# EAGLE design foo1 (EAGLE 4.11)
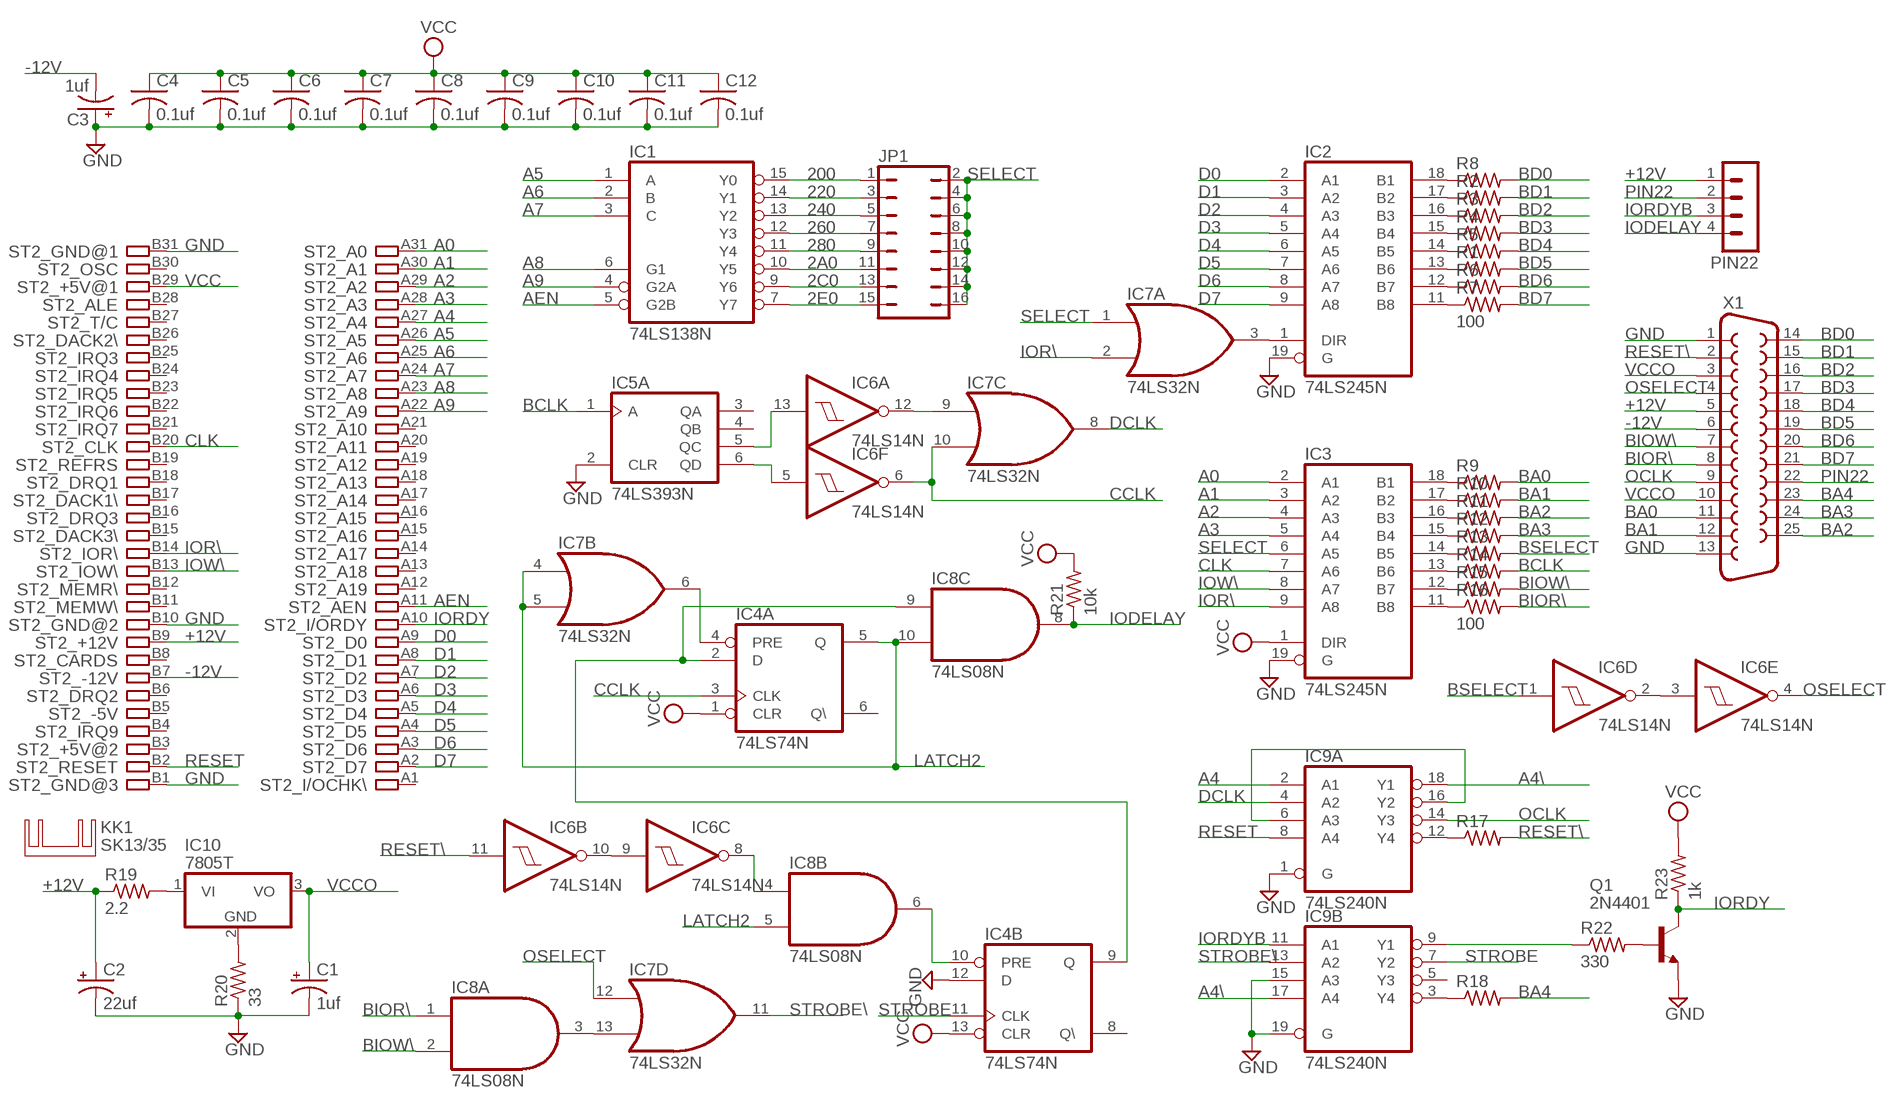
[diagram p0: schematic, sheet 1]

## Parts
C1  1uf  CPOL-USE5-10.5  [E5-10,5]
C2  22uf  CPOL-USE5-10.5  [E5-10,5]
C3  1uf  CPOL-USE5-10.5  [E5-10,5]
C4  0.1uf  C-US050-025X075  [C050-025X075]
C5  0.1uf  C-US050-025X075  [C050-025X075]
C6  0.1uf  C-US050-025X075  [C050-025X075]
C7  0.1uf  C-US050-025X075  [C050-025X075]
C8  0.1uf  C-US050-025X075  [C050-025X075]
C9  0.1uf  C-US050-025X075  [C050-025X075]
C10  0.1uf  C-US050-025X075  [C050-025X075]
C11  0.1uf  C-US050-025X075  [C050-025X075]
C12  0.1uf  C-US050-025X075  [C050-025X075]
IC1  74LS138N  [DIL16]
IC2  74LS245N  [DIL20]
IC3  74LS245N  [DIL20]
IC4  74LS74N  [DIL14]
IC5  74LS393N  [DIL14]
IC6  74LS14N  [DIL14]
IC7  74LS32N  [DIL14]
IC8  74LS08N  [DIL14]
IC9  74LS240N  [DIL20]
IC10  7805T  [TO220H]
JP1  JP8Q  [JP8Q]
KK1  SK13/35  [SK13/35]
PIN22  MA04-1  [MA04-1]
Q1  2N4401  2N4416  [TO92]
R1  R-US_0207/10  [0207/10]
R2  R-US_0207/10  [0207/10]
R3  R-US_0207/10  [0207/10]
R4  R-US_0207/10  [0207/10]
R5  R-US_0207/10  [0207/10]
R6  R-US_0207/10  [0207/10]
R7  100  R-US_0207/10  [0207/10]
R8  R-US_0207/10  [0207/10]
R9  R-US_0207/10  [0207/10]
R10  R-US_0207/10  [0207/10]
R11  R-US_0207/10  [0207/10]
R12  R-US_0207/10  [0207/10]
R13  R-US_0207/10  [0207/10]
R14  R-US_0207/10  [0207/10]
R15  R-US_0207/10  [0207/10]
R16  100  R-US_0207/10  [0207/10]
R17  R-US_0207/10  [0207/10]
R18  R-US_0207/10  [0207/10]
R19  2.2  R-US_0613/15  [P0613/15]
R20  33  R-US_0207/10  [0207/10]
R21  10k  R-US_0207/10  [0207/10]
R22  330  R-US_0207/10  [0207/10]
R23  1k  R-US_0207/10  [0207/10]
ST2  IBM8BIT  [IBM8BIT]
X1  F25H  [F25H]

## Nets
2A0: IC1.10(Y5) JP1.11
2C0: IC1.9(Y6) JP1.13
2E0: IC1.7(Y7) JP1.15
200: IC1.15(Y0) JP1.1
220: IC1.14(Y1) JP1.3
240: IC1.13(Y2) JP1.5
260: IC1.12(Y3) JP1.7
280: IC1.11(Y4) JP1.9
+12V [Power]: C2.+ PIN22.1 R19.1 ST2.B9 X1.5
-12V [Power]: C3.- ST2.B7 X1.6
A0: IC3.2(A1) ST2.A31
A1: IC3.3(A2) ST2.A30
A2: IC3.4(A3) ST2.A29
A3: IC3.5(A4) ST2.A28
A4: IC9.2(A:A1) ST2.A27
A4\: IC9.17(B:A4) IC9.18(A:Y1)
A5: IC1.1(A) ST2.A26
A6: IC1.2(B) ST2.A25
A7: IC1.3(C) ST2.A24
A8: IC1.6(G1) ST2.A23
A9: IC1.4(G2A) ST2.A22
AEN: IC1.5(G2B) ST2.A11
BA0: R9.2 X1.11
BA1: R10.2 X1.12
BA2: R11.2 X1.25
BA3: R12.2 X1.24
BA4: R18.2 X1.23
BCLK: IC5.1(A:A) R14.2
BD0: R8.2 X1.14
BD1: R2.2 X1.15
BD2: R3.2 X1.16
BD3: R4.2 X1.17
BD4: R5.2 X1.18
BD5: R1.2 X1.19
BD6: R6.2 X1.20
BD7: R7.2 X1.21
BIOR\: IC8.1(A:I0) R16.2 X1.8
BIOW\: IC8.2(A:I1) R15.2 X1.7
BSELECT: IC6.1(D:I) R13.2
CCLK: IC4.3(A:CLK) IC6.6(F:O) IC7.10(C:I1)
CLK: IC3.7(A6) ST2.B20
D0: IC2.2(A1) ST2.A9
D1: IC2.3(A2) ST2.A8
D2: IC2.4(A3) ST2.A7
D3: IC2.5(A4) ST2.A6
D4: IC2.6(A5) ST2.A5
D5: IC2.7(A6) ST2.A4
D6: IC2.8(A7) ST2.A3
D7: IC2.9(A8) ST2.A2
DCLK: IC7.8(C:O) IC9.4(A:A2)
GND [Power]: C1.- C2.- C3.+ C4.2 C5.2 C6.2 C7.2 C8.2 C9.2 C10.2 C11.2 C12.2 IC2.19(G) IC3.19(G) IC4.12(B:D) IC5.2(A:CLR) IC9.1(A:G) IC9.15(B:A3) IC9.19(B:G) Q1.3(E) R20.1 ST2.B1 ST2.B10 ST2.B31 X1.1 X1.13
IODELAY: IC8.8(C:O) PIN22.4 R21.1
IOR\: IC3.9(A8) IC7.2(A:I1) ST2.B14
IORDY: Q1.1(C) R23.1 ST2.A10
IORDYB: IC9.11(B:A1) PIN22.3
IOW\: IC3.8(A7) ST2.B13
LATCH2: IC4.5(A:Q) IC7.4(B:I0) IC7.5(B:I1) IC8.5(B:I1) IC8.10(C:I1)
N$1: IC2.1(DIR) IC7.3(A:O)
N$2 [Power]: IC10.2(GND) R20.2
N$3: IC2.13(B6) R1.1
N$4: IC2.17(B2) R2.1
N$5: IC2.16(B3) R3.1
N$6: IC2.15(B4) R4.1
N$7: IC2.14(B5) R5.1
N$8: IC2.12(B7) R6.1
N$9: IC2.11(B8) R7.1
N$10: IC2.18(B1) R8.1
N$11: IC3.18(B1) R9.1
N$12: IC3.17(B2) R10.1
N$13: IC3.16(B3) R11.1
N$14: IC3.15(B4) R12.1
N$15: IC3.14(B5) R13.1
N$16: IC3.13(B6) R14.1
N$17: IC3.12(B7) R15.1
N$18: IC3.11(B8) R16.1
N$19: IC9.12(A:Y4) R17.1
N$20: IC6.9(C:I) IC6.10(B:O)
N$21: IC6.2(D:O) IC6.3(E:I)
N$22: IC5.6(A:QD) IC6.5(F:I)
N$23: IC9.3(B:Y4) R18.1
N$24: IC5.5(A:QC) IC6.13(A:I)
N$25 [Power]: IC10.1(VI) R19.2
N$26: IC6.12(A:O) IC7.9(C:I0)
N$28: IC9.6(A:A3) IC9.16(A:Y2)
N$29: IC7.13(D:I1) IC8.3(A:O)
N$30: IC4.2(A:D) IC4.9(B:Q) IC8.9(C:I0)
N$32: IC9.9(B:Y1) R22.1
N$33: IC4.10(B:PRE) IC8.6(B:O)
N$34: IC6.8(C:O) IC8.4(B:I0)
N$36: IC4.4(A:PRE) IC7.6(B:O)
N$37: Q1.2(B) R22.2
OCLK: IC9.14(A:Y3) X1.9
OSELECT: IC6.4(E:O) IC7.12(D:I0) X1.4
PIN22: PIN22.2 X1.22
RESET: IC9.8(A:A4) ST2.B2
RESET\: IC6.11(B:I) R17.2 X1.2
SELECT: IC3.6(A5) IC7.1(A:I0) JP1.2 JP1.4 JP1.6 JP1.8 JP1.10 JP1.12 JP1.14 JP1.16
STROBE: IC4.11(B:CLK) IC9.7(B:Y2)
STROBE\: IC7.11(D:O) IC9.13(B:A2)
VCC [Power]: C4.1 C5.1 C6.1 C7.1 C8.1 C9.1 C10.1 C11.1 C12.1 IC3.1(DIR) IC4.1(A:CLR) IC4.13(B:CLR) R21.2 R23.2 ST2.B29
VCCO [Power]: C1.+ IC10.3(VO) X1.3 X1.10
Unconnected: IC4.6(A:Q\) IC4.8(B:Q\) IC5.3(A:QA) IC5.4(A:QB) IC5.8(B:QD) IC5.9(B:QC) IC5.10(B:QB) IC5.11(B:QA) IC5.12(B:CLR) IC5.13(B:A) IC8.11(D:O) IC8.12(D:I0) IC8.13(D:I1) IC9.5(B:Y3) ST2.A1 ST2.A12 ST2.A13 ST2.A14 ST2.A15 ST2.A16 ST2.A17 ST2.A18 ST2.A19 ST2.A20 ST2.A21 ST2.B3 ST2.B4 ST2.B5 ST2.B6 ST2.B8 ST2.B11 ST2.B12 ST2.B15 ST2.B16 ST2.B17 ST2.B18 ST2.B19 ST2.B21 ST2.B22 ST2.B23 ST2.B24 ST2.B25 ST2.B26 ST2.B27 ST2.B28 ST2.B30

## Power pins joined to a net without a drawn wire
GND: IC1.8(GND) IC2.10(GND) IC3.10(GND) IC4.7(P:GND) IC5.7(P:GND) IC6.7(P:GND) IC7.7(P:GND) IC8.7(P:GND) IC9.10(P:GND)
VCC: IC1.16(VCC) IC2.20(VCC) IC3.20(VCC) IC4.14(P:VCC) IC5.14(P:VCC) IC6.14(P:VCC) IC7.14(P:VCC) IC8.14(P:VCC) IC9.20(P:VCC)

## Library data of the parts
C1-C3 = rcl:CPOL-US: POLARIZED CAPACITOR, American symbol
C4-C12 = rcl:C-US: CAPACITOR, American symbol
IC1 = 74xx-us:74*138: 3-line to 8-line DECODER/DEMULTIPLEXER
IC2 IC3 = 74xx-us:74*245: Octal BUS TRANSCEIVER, 3-state
IC4 = 74xx-us:74*74: Dual D type positive edge triggered FLIP FLOP, preset and clear
IC5 = 74xx-us:74*393: Dual 4-bit decade and binary COUNTER
IC6 = 74xx-us:74*14: Hex schmitt trigger INVERTER
IC7 = 74xx-us:74*32: Quad 2-input OR gate
IC8 = 74xx-us:74*08: Quad 2-input AND gate
IC9 = 74xx-us:74*240: Octal BUFFER and LINE DRIVER, 3-state
IC10 = linear:78*: Positive VOLTAGE REGULATOR
JP1 = jumper:JP8Q: JUMPER
KK1 = heatsink:SK13/35: HEATSINK
PIN22 = con-lstb:MA04-1: PIN HEADER
Q1 = transistor-npn:2N4416: NPN Transistor
R1-R23 = rcl:R-US_: RESISTOR, American symbol
ST2 = con-pc:IBM8BIT: 8-bit CARD IBM/PC-AT
X1 = con-subd:F25: SUB-D

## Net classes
1 Power: width 0.762 mm, drill 0.254 mm

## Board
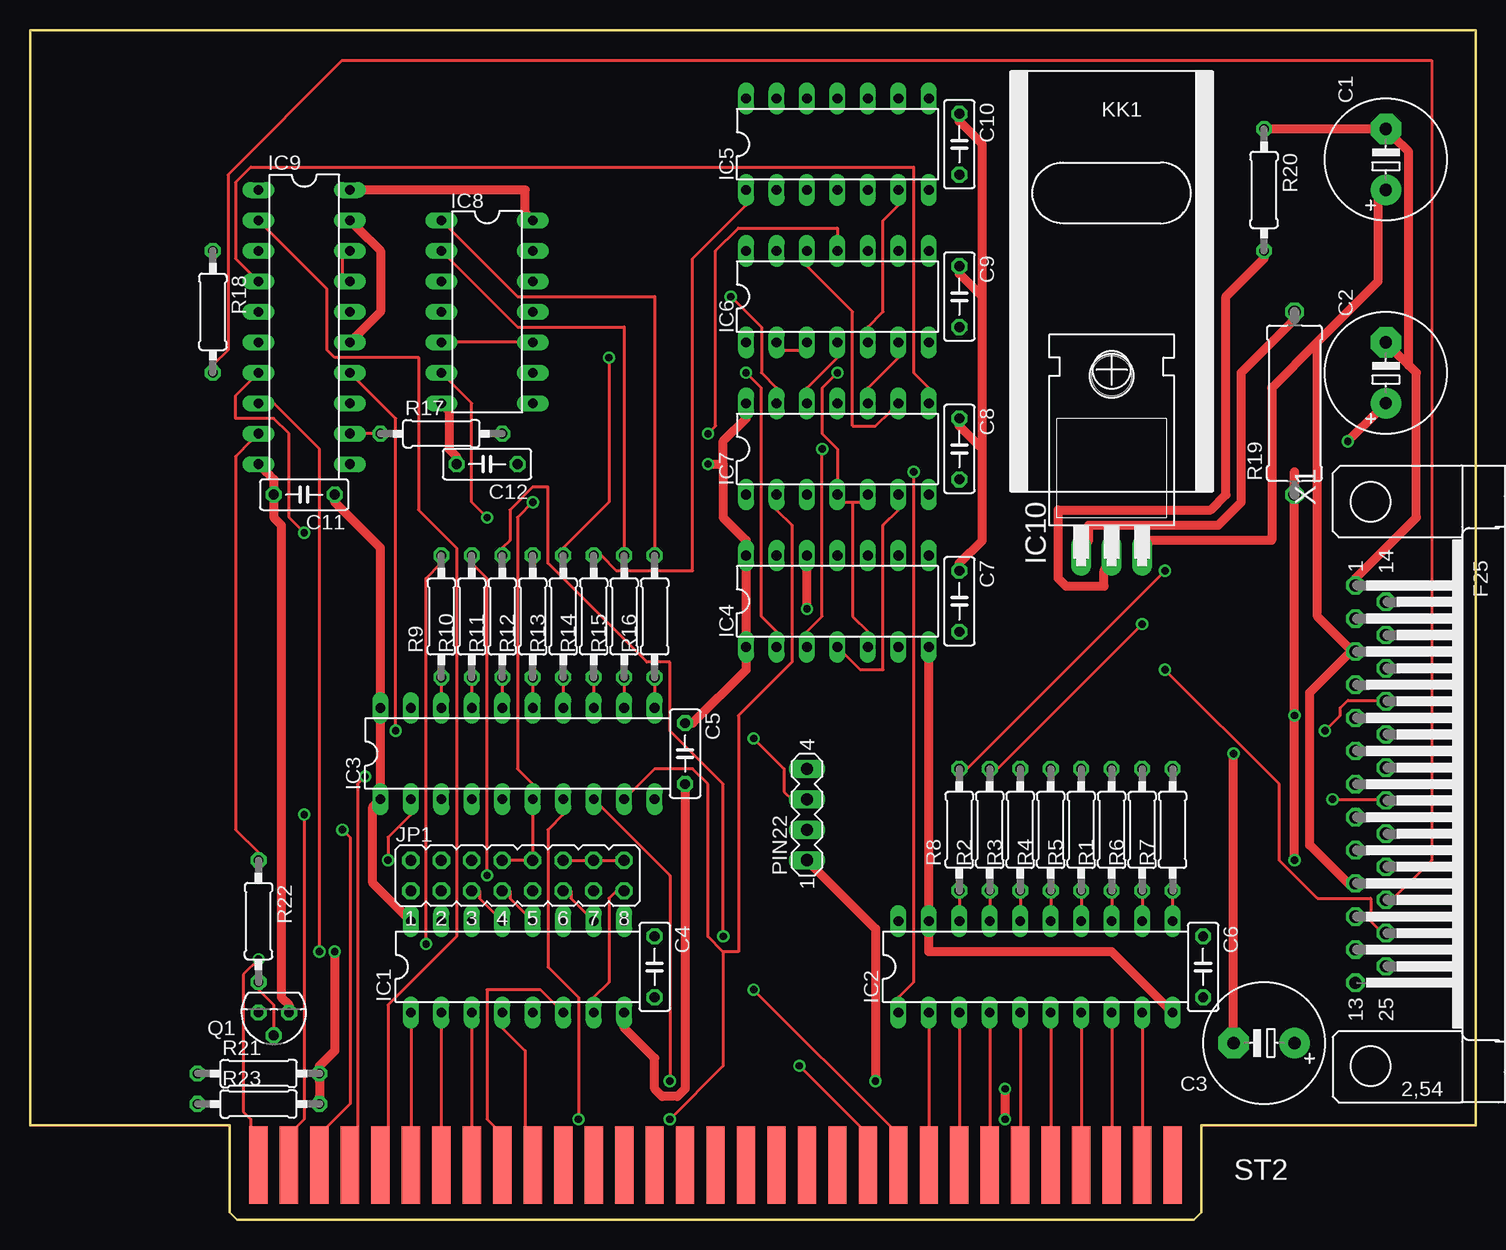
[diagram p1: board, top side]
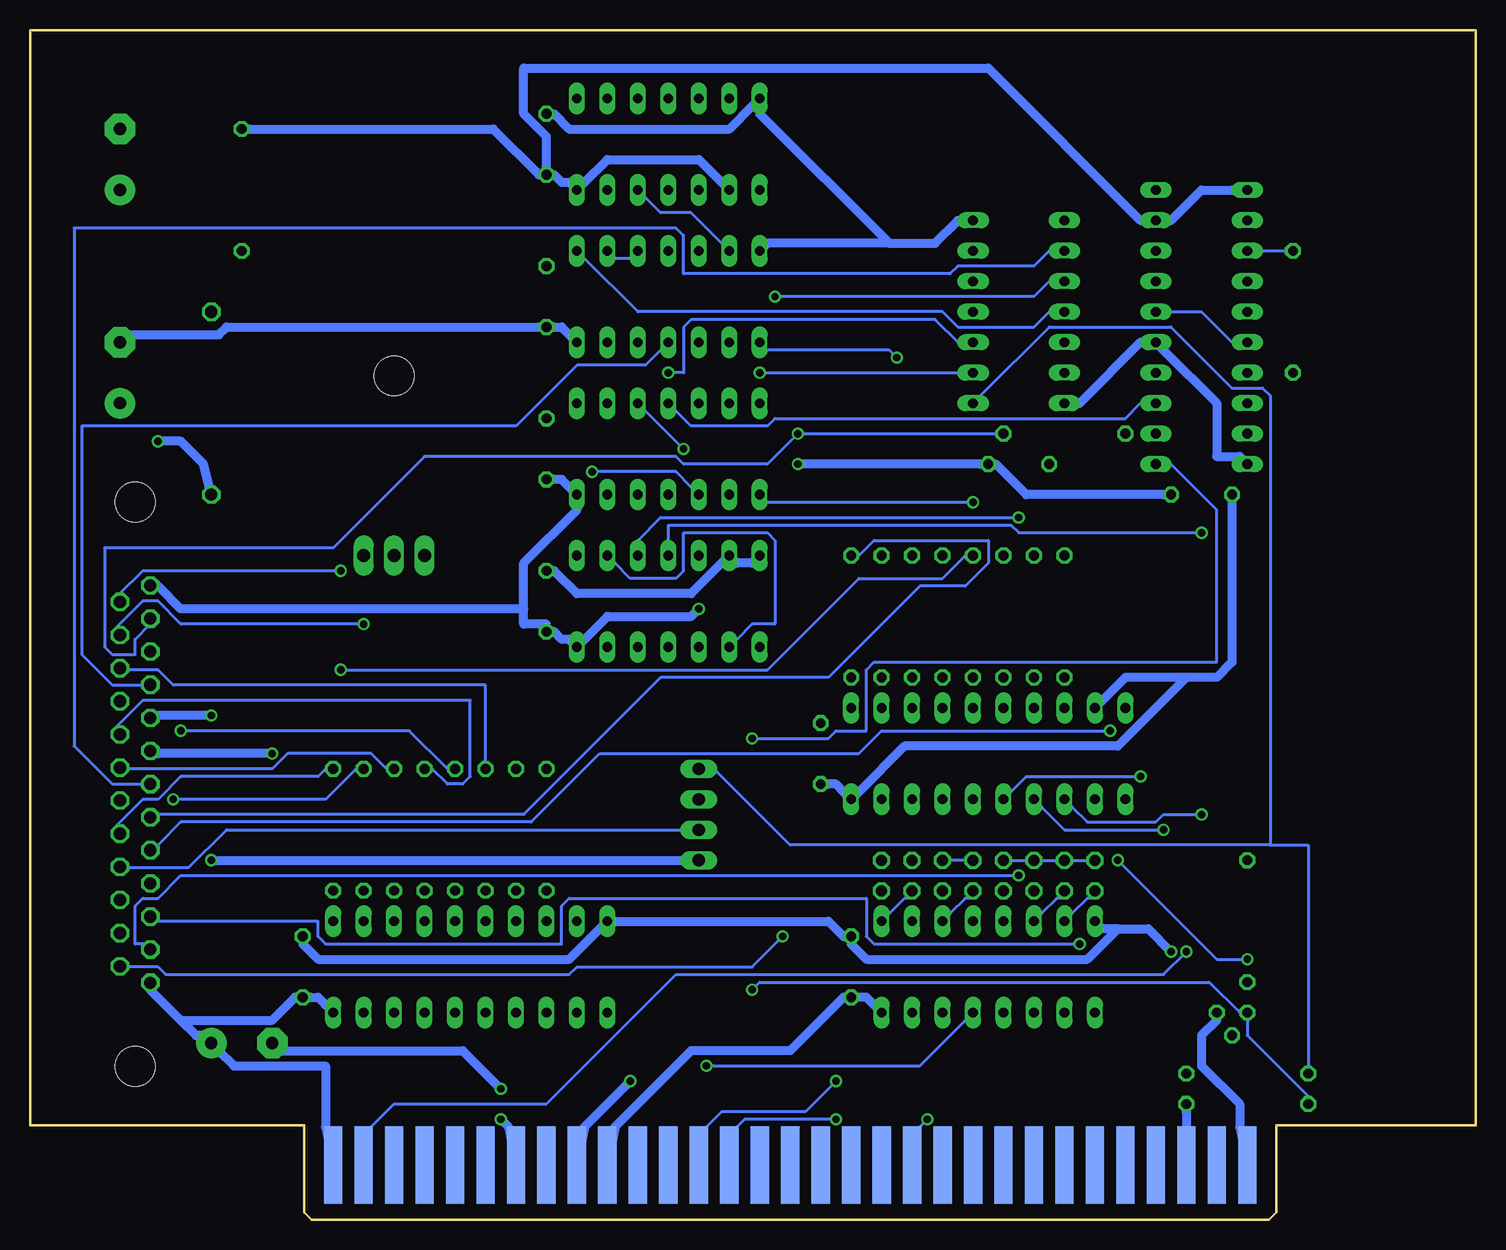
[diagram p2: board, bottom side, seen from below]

Size 120.52 x 99.19 mm. Coordinates in mm from the lower left corner, seen from the top.
Outline: 0,7.87 0,99.19 120.52,99.19 120.52,7.87 97.66,7.87 97.66,0.64 97.03,0 17.27,0 16.64,0.64 16.64,7.87 0.13,7.87
Copper layers (1*16): Top 0.035mm / dielectric 1.5mm / Bottom 0.035mm
Design rules "olimex10mil": minimum track width 10mil, minimum drill 24mil, track to track 10mil, track to pad 10mil, pad to pad 10mil, via to via 10mil, smd to smd 10mil, copper to edge 40mil, drill to drill 10mil, minimum pad ring 10mil, minimum via ring 8mil, stop-mask expansion 0mil, vias tented up to drill 0mil, thermal gap 10mil

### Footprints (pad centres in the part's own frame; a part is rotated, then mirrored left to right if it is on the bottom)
E5-10,5 = drill 1.016 pad 2.54 round: + -2.54,0 | drill 1.016 pad 2.54 octagon: - 2.54,0
C050-025X075 = drill 0.813 octagon: 1 -2.54,0; 2 2.54,0
DIL16 = drill 0.813 long: 1 -8.89,-3.81; 2 -6.35,-3.81; 3 -3.81,-3.81; 4 -1.27,-3.81; 5 1.27,-3.81; 6 3.81,-3.81; 7 6.35,-3.81; 8 8.89,-3.81; 9 8.89,3.81; 10 6.35,3.81; 11 3.81,3.81; 12 1.27,3.81; 13 -1.27,3.81; 14 -3.81,3.81; 15 -6.35,3.81; 16 -8.89,3.81
DIL20 = drill 0.813 long: 1 -11.43,-3.81; 2 -8.89,-3.81; 3 -6.35,-3.81; 4 -3.81,-3.81; 5 -1.27,-3.81; 6 1.27,-3.81; 7 3.81,-3.81; 8 6.35,-3.81; 9 8.89,-3.81; 10 11.43,-3.81; 11 11.43,3.81; 12 8.89,3.81; 13 6.35,3.81; 14 3.81,3.81; 15 1.27,3.81; 16 -1.27,3.81; 17 -3.81,3.81; 18 -6.35,3.81; 19 -8.89,3.81; 20 -11.43,3.81
DIL14 = drill 0.813 long: 1 -7.62,-3.81; 2 -5.08,-3.81; 3 -2.54,-3.81; 4 0,-3.81; 5 2.54,-3.81; 6 5.08,-3.81; 7 7.62,-3.81; 8 7.62,3.81; 9 5.08,3.81; 10 2.54,3.81; 11 0,3.81; 12 -2.54,3.81; 13 -5.08,3.81; 14 -7.62,3.81
TO220H = drill 1.118 long: 1 -2.54,-10.16; 2 0,-10.16; 3 2.54,-10.16 | hole 3.302: 0,4.826
JP8Q = drill 0.914 octagon: 1 -8.89,-1.27; 2 -8.89,1.27; 3 -6.35,-1.27; 4 -6.35,1.27; 5 -3.81,-1.27; 6 -3.81,1.27; 7 -1.27,-1.27; 8 -1.27,1.27; 9 1.27,-1.27; 10 1.27,1.27; 11 3.81,-1.27; 12 3.81,1.27; 13 6.35,-1.27; 14 6.35,1.27; 15 8.89,-1.27; 16 8.89,1.27
MA04-1 = drill 1.016 long: 1 -3.81,0; 2 -1.27,0; 3 1.27,0; 4 3.81,0
TO92 = drill 0.813 octagon: 1 1.27,0; 2 0,1.905; 3 -1.27,0
0207/10 = drill 0.813 octagon: 1 -5.08,0; 2 5.08,0
P0613/15 = drill 1.016 octagon: 1 -7.62,0; 2 7.62,0
IBM8BIT = smd 1.524 x 6.477: A1 -25.4,5.08; A2 -27.94,5.08; A3 -30.48,5.08; A4 -33.02,5.08; A5 -35.56,5.08; A6 -38.1,5.08; A7 -40.64,5.08; A8 -43.18,5.08; A9 -45.72,5.08; A10 -48.26,5.08; A11 -50.8,5.08; A12 -53.34,5.08; A13 -55.88,5.08; A14 -58.42,5.08; A15 -60.96,5.08; A16 -63.5,5.08; A17 -66.04,5.08; A18 -68.58,5.08; A19 -71.12,5.08; A20 -73.66,5.08; A21 -76.2,5.08; A22 -78.74,5.08; A23 -81.28,5.08; A24 -83.82,5.08; A25 -86.36,5.08; A26 -88.9,5.08; A27 -91.44,5.08; A28 -93.98,5.08; A29 -96.52,5.08; A30 -99.06,5.08; A31 -101.6,5.08 | smd 1.524 x 6.477 bottom: B1 -25.4,5.08; B2 -27.94,5.08; B3 -30.48,5.08; B4 -33.02,5.08; B5 -35.56,5.08; B6 -38.1,5.08; B7 -40.64,5.08; B8 -43.18,5.08; B9 -45.72,5.08; B10 -48.26,5.08; B11 -50.8,5.08; B12 -53.34,5.08; B13 -55.88,5.08; B14 -58.42,5.08; B15 -60.96,5.08; B16 -63.5,5.08; B17 -66.04,5.08; B18 -68.58,5.08; B19 -71.12,5.08; B20 -73.66,5.08; B21 -76.2,5.08; B22 -78.74,5.08; B23 -81.28,5.08; B24 -83.82,5.08; B25 -86.36,5.08; B26 -88.9,5.08; B27 -91.44,5.08; B28 -93.98,5.08; B29 -96.52,5.08; B30 -99.06,5.08; B31 -101.6,5.08
F25H = drill 1.016 octagon: 1 -16.561,-1.27; 2 -13.792,-1.27; 3 -11.049,-1.27; 4 -8.28,-1.27; 5 -5.512,-1.27; 6 -2.769,-1.27; 7 0,-1.27; 8 2.769,-1.27; 9 5.512,-1.27; 10 8.28,-1.27; 11 11.049,-1.27; 12 13.792,-1.27; 13 16.561,-1.27; 14 -15.189,1.27; 15 -12.421,1.27; 16 -9.652,1.27; 17 -6.909,1.27; 18 -4.14,1.27; 19 -1.372,1.27; 20 1.372,1.27; 21 4.14,1.27; 22 6.909,1.27; 23 9.652,1.27; 24 12.421,1.27; 25 15.189,1.27 | hole 3.302: -23.52,0; 23.52,0

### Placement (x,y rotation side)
C1  113.03,88.39 90 top
C2  113.03,70.61 90 top
C3  102.87,14.73 180 top
C4  52.07,21.08 270 top
C5  54.61,38.86 270 top
C6  97.79,21.08 270 top
C7  77.47,51.56 270 top
C8  77.47,64.26 270 top
C9  77.47,76.96 270 top
C10  77.47,89.66 270 top
C11  22.86,60.45 180 top
C12  38.1,62.99 180 top
IC1  40.64,21.08 0 top
IC2  83.82,21.08 0 top
IC3  40.64,38.86 0 top
IC4  67.31,51.56 0 top
IC5  67.31,89.66 0 top
IC6  67.31,76.96 0 top
IC7  67.31,64.26 0 top
IC8  38.1,75.69 270 top
IC9  22.86,74.42 270 top
IC10  90.17,65.53 0 top
JP1  40.64,28.7 0 top
KK1  90.17,82.04 90 top
PIN22  64.77,33.78 90 top
Q1  20.32,17.27 180 top
R1  90.17,32.51 90 top
R2  80.01,32.51 90 top
R3  82.55,32.51 90 top
R4  85.09,32.51 90 top
R5  87.63,32.51 90 top
R6  92.71,32.51 90 top
R7  95.25,32.51 90 top
R8  77.47,32.51 90 top
R9  34.29,50.29 90 top
R10  36.83,50.29 90 top
R11  39.37,50.29 90 top
R12  41.91,50.29 90 top
R13  44.45,50.29 90 top
R14  46.99,50.29 90 top
R15  49.53,50.29 90 top
R16  52.07,50.29 90 top
R17  34.29,65.53 0 top
R18  15.24,75.69 270 top
R19  105.41,68.07 90 top
R20  102.87,85.85 270 top
R21  19.05,12.19 0 top
R22  19.05,24.89 270 top
R23  19.05,9.65 0 top
ST2  120.65,-0.51 0 top
X1  111.76,36.32 270 top

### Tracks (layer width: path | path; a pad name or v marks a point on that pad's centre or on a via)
2A0
  Top 0.254: IC1.10 46.36,25.53 45.09,26.8 45.09,27.43 JP1.11
2C0
  Bottom 0.254: IC1.9 48.9,25.53 47.62,26.8 46.99,26.8 JP1.13
2E0
  Top 0.254: IC1.7 46.99,18.54 48.26,19.81 48.26,26.8 48.9,27.43 JP1.15
200
  Bottom 0.254: IC1.15 33.66,25.53 32.39,26.8 31.75,26.8 JP1.1
220
  Bottom 0.254: IC1.14 36.2,25.53 34.93,26.8 34.29,26.8 JP1.3
240
  Top 0.254: IC1.13 38.73,25.53 37.47,26.8 37.47,27.43 JP1.5
260
  Top 0.254: IC1.12 41.28,25.53 40.01,26.8 40.01,27.43 JP1.7
280
  Bottom 0.254: IC1.11 43.82,25.53 42.55,26.8 41.91,26.8 JP1.9
+12V  (via drill 0.61)
  Top 0.762: v70.49,11.56 70.49,24.26 65.41,29.34 PIN22.1 | v109.86,64.9 112.4,67.44 C2.+ | R19.1 105.41,62.36 v105.41,42.04 v105.41,29.97
  Bottom 0.762: v70.49,11.56 74.3,7.75 ST2.B9 | v109.86,64.9 107.95,64.9 106.05,62.99 R19.1 | v105.41,42.04 109.86,42.04 X1.5 | v105.41,29.97 66.04,29.97 PIN22.1
-12V  (via drill 0.61)
  Top 0.762: v100.33,38.86 100.33,15.37 C3.- | v81.28,10.92 v81.28,8.38
  Bottom 0.762: v100.33,38.86 109.86,38.86 X1.6 | v81.28,8.38 80.65,7.75 ST2.B7 | v81.28,10.92 84.46,14.1 99.7,14.1 C3.-
A0  (via drill 0.61)
  Top 0.254: v29.84,29.97 29.84,31.88 31.75,33.78 IC3.2 | v19.05,21.72 17.78,20.45 17.78,9.02 18.42,8.38 18.42,7.75 ST2.A31
  Bottom 0.254: v29.84,29.97 21.59,21.72 v19.05,21.72
A1  (via drill 0.61)
  Top 0.254: v22.86,33.78 22.86,8.38 22.23,7.75 ST2.A30
  Bottom 0.254: v22.86,33.78 26.04,33.78 26.67,33.15 32.39,33.15 33.66,34.42 IC3.3
A2  (via drill 0.61)
  Top 0.254: v26.04,32.51 26.67,31.88 26.67,9.65 24.77,7.75 ST2.A29
  Bottom 0.254: v26.04,32.51 34.29,32.51 36.2,34.42 IC3.4
A3  (via drill 0.61)
  Top 0.254: v27.94,36.96 27.31,36.32 27.31,7.75 ST2.A28
  Bottom 0.254: v27.94,36.96 37.47,36.96 38.73,35.69 IC3.5
A4
  Top 0.254: IC9.2 19.69,82.68 24.77,77.6 24.77,72.52 25.4,71.88 32.39,71.88 32.39,59.18 35.56,56.01 35.56,23.62 29.84,17.91 29.84,7.75 ST2.A27
A4\
  Top 0.254: IC9.17 26.04,78.87 26.04,80.14 IC9.18
A5
  Top 0.254: IC1.1 31.75,16 31.75,7.75 ST2.A26
A6
  Top 0.254: IC1.2 34.29,16 34.29,7.75 ST2.A25
A7
  Top 0.254: IC1.3 36.83,16 36.83,7.75 ST2.A24
A8
  Top 0.254: IC1.6 43.82,17.91 42.55,19.18 38.1,19.18 38.1,8.38 38.73,7.75 ST2.A23
A9
  Top 0.254: IC1.4 39.37,16 41.28,14.1 41.28,7.75 ST2.A22
AEN  (via drill 0.61)
  Top 0.254: v64.14,12.83 69.22,7.75 ST2.A11
  Bottom 0.254: v64.14,12.83 46.36,12.83 42.55,16.64 IC1.5
BA0  (via drill 0.61)
  Top 0.254: v33.02,22.99 33.02,53.47 34.29,54.74 R9.2
  Bottom 0.254: v33.02,22.99 50.17,22.99 50.8,23.62 50.8,26.8 75.56,26.8 76.2,26.16 76.2,22.99 95.89,22.99 96.52,23.62 96.52,24.89 109.86,24.89 X1.11
BA1  (via drill 0.61)
  Top 0.254: v38.1,28.7 38.1,53.47 36.83,54.74 R10.2
  Bottom 0.254: v38.1,28.7 107.95,28.7 109.86,26.8 111.12,26.8 111.76,26.16 111.76,22.99 110.49,22.99 X1.12
BA2  (via drill 0.61)
  Top 0.254: v57.79,23.62 57.79,36.32 53.34,40.77 53.34,46.48 51.44,46.48 43.18,54.74 43.18,61.09 41.91,61.09 40.01,59.18 40.01,56.64 39.37,56.01 R11.2
  Bottom 0.254: v57.79,23.62 60.33,21.08 74.93,21.08 75.56,20.45 109.22,20.45 109.86,21.08 112.4,21.08 X1.25
BA3  (via drill 0.61)
  Top 0.254: v94.62,45.85 104.14,36.32 104.14,29.97 107.31,26.8 111.76,26.8 111.76,24.89 112.4,24.26 X1.24
  Bottom 0.254: v94.62,45.85 59.06,45.85 51.44,53.47 44.45,53.47 42.55,55.37 R12.2
BA4
  Top 0.254: R18.2 15.24,71.25 16.51,72.52 16.51,87.12 26.04,96.65 116.84,96.65 116.84,29.97 113.67,26.8 X1.23
BCLK
  Top 0.254: R14.2 47.62,55.37 48.9,54.1 55.25,54.1 55.25,80.14 59.69,84.58 IC5.1
BD0  (via drill 0.61)
  Top 0.254: v94.62,54.1 78.11,37.59 R8.2
  Bottom 0.254: v94.62,54.1 111.12,54.1 113.03,52.2 X1.14
BD1  (via drill 0.61)
  Top 0.254: v92.71,49.66 80.65,37.59 R2.2
  Bottom 0.254: v92.71,49.66 107.95,49.66 109.86,51.56 111.12,51.56 113.67,49.02 X1.15
BD2
  Bottom 0.254: R3.2 82.55,38.23 82.55,44.58 108.59,44.58 109.86,45.85 112.4,45.85 X1.16
BD3  (via drill 0.61)
  Top 0.254: v107.95,40.77 109.22,42.04 109.22,42.67 109.86,43.31 112.4,43.31 X1.17
  Bottom 0.254: v107.95,40.77 88.9,40.77 85.73,37.59 R4.2
BD4
  Bottom 0.254: R5.2 87,37.59 85.73,36.32 84.46,36.32 83.82,36.96 83.82,43.31 111.12,43.31 113.67,40.77 X1.18
BD5
  Bottom 0.254: R1.2 90.81,37.59 92.08,38.86 99.06,38.86 100.33,37.59 112.4,37.59 X1.19
BD6  (via drill 0.61)
  Top 0.254: v108.59,35.05 112.4,35.05 X1.20
  Bottom 0.254: v108.59,35.05 95.89,35.05 93.34,37.59 R6.2
BD7
  Bottom 0.254: R7.2 95.89,37.59 96.52,36.96 107.95,36.96 109.86,35.05 111.12,35.05 113.67,32.51 X1.21
BIOR\
  Top 0.254: IC8.1 34.93,82.68 40.64,76.96 52.07,76.96 52.07,56.01 R16.2
  Bottom 0.254: X1.8 109.86,33.78 79.38,33.78 67.95,45.21 53.98,45.21 46.36,52.83 42.55,52.83 40.64,54.74 40.64,56.64 50.17,56.64 51.44,55.37 R16.2
BIOW\
  Top 0.254: IC8.2 34.93,80.14 40.64,74.42 49.53,74.42 49.53,56.01 R15.2
  Bottom 0.254: X1.7 111.12,36.32 113.67,36.32 116.84,39.5 116.84,82.68 66.68,82.68 66.04,82.04 66.04,78.87 43.82,78.87 43.18,79.5 36.83,79.5 35.56,80.77 IC8.2
BSELECT  (via drill 0.61)
  Top 0.254: v48.26,71.88 48.26,59.82 44.45,56.01 R13.2
  Bottom 0.254: v48.26,71.88 48.9,72.52 59.06,72.52 IC6.1
CCLK  (via drill 0.61)
  Top 0.254: v66.04,64.26 66.04,50.29 64.77,49.02 IC4.3 | IC6.6 72.39,71.88 69.85,69.34 IC7.10
  Bottom 0.254: v66.04,64.26 69.22,67.44 IC7.10
CLK  (via drill 0.61)
  Top 0.254: v45.72,8.38 45.72,18.54 43.18,21.08 43.18,32.51 44.45,33.78 IC3.7
  Bottom 0.254: v45.72,8.38 46.36,7.75 ST2.B20
D0
  Top 0.254: IC2.2 74.93,16 74.93,7.75 ST2.A9
D1
  Top 0.254: IC2.3 77.47,16 77.47,7.75 ST2.A8
D2
  Top 0.254: IC2.4 80.01,16 80.01,7.75 ST2.A7
D3
  Top 0.254: IC2.5 82.55,16 82.55,7.75 ST2.A6
D4
  Top 0.254: IC2.6 85.09,16 85.09,7.75 ST2.A5
D5
  Top 0.254: IC2.7 87.63,16 87.63,7.75 ST2.A4
D6
  Top 0.254: IC2.8 90.17,16 90.17,7.75 ST2.A3
D7
  Top 0.254: IC2.9 92.71,16 92.71,7.75 ST2.A2
DCLK
  Top 0.254: IC9.4 18.42,78.87 17.15,80.14 17.15,86.49 18.42,87.76 73.66,87.76 73.66,70.61 74.93,69.34 IC7.8
GND  (via drill 0.61)
  Top 0.762: C12.2 35.56,63.63 34.93,64.26 34.93,67.44 IC8.7 | IC9.19 27.31,82.68 29.21,80.77 29.21,75.69 27.31,73.79 IC9.15 | IC9.10 19.69,62.36 20.32,61.72 20.32,61.09 C11.2 20.32,59.82 20.32,58.55 20.96,57.91 20.96,18.54 21.59,17.91 Q1.3 | IC1.8 49.53,16 52.07,13.46 52.07,10.92 52.71,10.29 53.98,10.29 54.61,10.92 54.61,35.69 C5.2 | 114.94,71.25 113.67,72.52 C2.- | 114.94,71.25 115.57,70.61 115.57,58.55 110.49,53.47 X1.1 | 114.94,71.25 114.94,89.03 113.67,90.3 C1.- 112.4,90.93 103.51,90.93 R20.1 | IC4.7 74.93,46.48 74.93,26.16 IC2.19 74.93,23.62 74.93,22.35 90.17,22.35 94.62,17.91 IC2.10 | v64.77,50.93 64.77,54.1 IC4.12
  Bottom 0.762: IC1.8 50.17,17.91 50.8,18.54 51.44,18.54 C4.2 52.71,18.54 57.15,14.1 65.41,14.1 71.75,7.75 ST2.B10 | IC9.1 20.32,85.85 22.86,85.85 25.4,83.31 IC9.19 27.94,83.31 40.64,96.01 79.38,96.01 79.38,92.2 77.47,90.3 77.47,87.76 C10.2 | IC8.7 33.02,68.07 27.94,73.15 IC9.15 26.04,72.52 21.59,68.07 21.59,63.63 19.69,63.63 IC9.10 | Q1.3 21.59,16.64 22.86,15.37 22.86,12.83 19.69,9.65 19.69,7.75 ST2.B31 | C5.2 53.98,36.32 53.34,36.32 52.71,35.69 IC3.10 51.44,35.69 47.62,39.5 29.84,39.5 24.13,45.21 | 24.13,45.21 21.59,45.21 20.32,46.48 20.32,59.82 C11.2 | 24.13,45.21 29.21,45.21 31.12,43.31 IC3.19 | IC5.2 62.87,86.49 64.77,88.39 72.39,88.39 74.3,86.49 IC5.7 75.56,86.49 76.2,86.49 76.84,87.12 C10.2 | IC6.7 75.56,73.79 76.2,74.42 76.84,74.42 C9.2 78.11,74.42 104.14,74.42 104.78,73.79 112.4,73.79 C2.- | IC2.10 95.89,17.91 96.52,18.54 97.16,18.54 C6.2 98.43,18.54 100.33,16.64 107.95,16.64 | 107.95,16.64 106.68,15.37 106.05,15.37 C3.+ 104.78,14.1 103.51,12.83 95.89,12.83 95.89,7.75 ST2.B1 | 107.95,16.64 110.49,19.18 X1.13 | C8.2 76.84,61.72 76.2,61.72 75.56,61.09 IC7.7 74.93,59.18 79.38,54.74 79.38,50.93 | v64.77,50.93 65.41,50.29 72.39,50.29 74.3,48.39 IC4.7 75.56,48.39 76.2,48.39 76.84,49.02 C7.2 77.47,49.66 79.38,49.66 79.38,50.93 | 79.38,50.93 107.95,50.93 109.86,52.83 X1.1 | C10.2 78.11,87.12 81.92,90.93 102.24,90.93 R20.1
IODELAY
  Bottom 0.254: 17.15,31.24 57.15,31.24 63.5,37.59 PIN22.4 | 17.15,31.24 13.97,31.24 13.97,12.83 R21.1 | 17.15,31.24 17.15,68.71 17.78,69.34 20.32,69.34 25.4,74.42 35.56,74.42 41.28,68.71 IC8.8
IOR\  (via drill 0.61)
  Top 0.254: 57.79,22.35 56.52,23.62 56.52,36.32 55.25,37.59 52.07,37.59 50.17,35.69 IC3.9 | 57.79,22.35 59.06,22.35 59.06,42.04 63.5,46.48 63.5,57.91 62.23,59.18 IC7.2 | v53.34,8.38 57.79,12.83 57.79,22.35
  Bottom 0.254: v53.34,8.38 60.96,8.38 61.6,7.75 ST2.B14
IORDY  (via drill 0.61)
  Top 0.254: v60.33,19.18 71.75,7.75 ST2.A10
  Bottom 0.254: R23.1 13.97,10.29 19.05,15.37 19.05,16.64 Q1.1 19.69,17.27 22.23,19.81 59.69,19.81 v60.33,19.18
IORDYB  (via drill 0.61)
  Top 0.254: v60.33,40.13 62.87,37.59 62.87,35.69 63.5,35.05 PIN22.3
  Bottom 0.254: v60.33,40.13 53.98,40.13 53.34,40.77 50.8,40.77 50.8,45.85 50.17,46.48 21.59,46.48 21.59,59.18 25.4,62.99 IC9.11
IOW\  (via drill 0.61)
  Top 0.254: v53.34,11.56 53.34,28.7 47.62,34.42 IC3.8
  Bottom 0.254: v53.34,11.56 55.88,9.02 62.87,9.02 64.14,7.75 ST2.B13
LATCH2  (via drill 0.61)
  Top 0.254: IC8.5 35.56,73.15 40.64,73.15 IC8.10 | 68.58,59.82 69.22,59.82 IC7.5 | 68.58,59.82 67.95,59.82 IC7.4 67.31,61.72 67.31,64.26 66.04,65.53 66.04,69.34 v67.31,70.61 | 68.58,59.82 68.58,50.29 69.85,49.02 IC4.5
  Bottom 0.254: v67.31,70.61 66.04,70.61 66.04,74.42 65.41,75.06 45.09,75.06 43.18,73.15 IC8.10
N$1  (via drill 0.61)
  Top 0.254: v73.66,62.36 73.66,19.81 72.39,18.54 IC2.1
  Bottom 0.254: v73.66,62.36 66.68,62.36 65.41,61.09 IC7.3
N$2
  Top 0.762: R20.2 102.87,80.14 99.7,76.96 99.7,60.45 98.43,59.18 85.73,59.18 85.73,53.47 86.36,52.83 89.54,52.83 89.54,54.1 IC10.2
N$3
  Top 0.254: IC2.13 90.17,26.16 90.17,26.8 R1.1
N$4
  Top 0.254: IC2.17 80.01,26.16 80.01,26.8 R2.1
N$5
  Top 0.254: IC2.16 82.55,26.16 82.55,26.8 R3.1
N$6
  Top 0.254: IC2.15 85.09,26.16 85.09,26.8 R4.1
N$7
  Top 0.254: IC2.14 87.63,26.16 87.63,26.8 R5.1
N$8
  Top 0.254: IC2.12 92.71,26.16 92.71,26.8 R6.1
N$9
  Top 0.254: IC2.11 95.25,26.16 95.25,26.8 R7.1
N$10
  Top 0.254: IC2.18 77.47,26.16 77.47,26.8 R8.1
N$11
  Top 0.254: IC3.18 34.29,43.94 34.29,44.58 R9.1
N$12
  Top 0.254: IC3.17 36.83,43.94 36.83,44.58 R10.1
N$13
  Top 0.254: IC3.16 39.37,43.94 39.37,44.58 R11.1
N$14
  Top 0.254: IC3.15 41.91,43.94 41.91,44.58 R12.1
N$15
  Top 0.254: IC3.14 44.45,43.94 44.45,44.58 R13.1
N$16
  Top 0.254: IC3.13 46.99,43.94 46.99,44.58 R14.1
N$17
  Top 0.254: IC3.12 49.53,43.94 49.53,44.58 R15.1
N$18
  Top 0.254: IC3.11 52.07,43.94 52.07,44.58 R16.1
N$19
  Top 0.254: IC9.12 27.94,65.53 28.58,65.53 R17.1
N$20
  Bottom 0.254: IC6.10 70.49,80.14 71.75,80.14 IC6.9
N$21
  Top 0.254: IC6.2 62.87,72.52 64.14,72.52 IC6.3
N$22
  Top 0.254: IC6.5 69.85,74.42 71.12,75.69 71.12,83.31 72.39,84.58 IC5.6
N$23
  Bottom 0.254: R18.1 15.88,80.77 17.78,80.77 IC9.3
N$24
  Bottom 0.254: IC6.13 62.87,81.41 65.41,83.95 67.95,83.95 69.22,85.22 IC5.5
N$25
  Top 0.762: R19.2 105.41,75.06 100.97,70.61 100.97,59.82 99.06,57.91 88.27,57.91 88.27,56.64 IC10.1
N$26
  Top 0.254: IC7.9 71.75,67.44 70.49,66.17 68.58,66.17 68.58,75.69 64.77,79.5 IC6.12
N$28
  Bottom 0.254: IC9.6 20.32,73.15 22.86,75.69 25.4,75.69 IC9.16
N$29  (via drill 0.61)
  Top 0.254: v58.42,76.96 60.96,74.42 60.96,70.61 62.23,69.34 IC7.13
  Bottom 0.254: v58.42,76.96 36.83,76.96 35.56,78.23 IC8.3
N$30  (via drill 0.61)
  Top 0.254: v59.69,70.61 60.96,69.34 60.96,50.29 62.23,49.02 IC4.2
  Bottom 0.254: v59.69,70.61 43.18,70.61 IC8.9 | IC4.9 71.75,54.74 70.49,53.47 66.68,53.47 66.04,54.1 66.04,57.28 59.06,57.28 58.42,56.64 58.42,49.66 60.33,49.66 61.6,48.39 IC4.2
N$32
  Top 0.254: R22.1 19.05,30.61 17.15,32.51 17.15,63.63 18.42,64.9 IC9.9
N$33  (via drill 0.61)
  Top 0.254: v38.1,58.55 36.83,59.82 36.83,68.07 34.93,69.98 IC8.6
  Bottom 0.254: v38.1,58.55 67.95,58.55 69.85,56.64 IC4.10
N$34
  Bottom 0.254: IC8.4 35.56,75.69 36.83,74.42 43.18,74.42 44.45,75.69 69.85,75.69 74.3,80.14 IC6.8
N$36
  Top 0.254: IC4.4 67.95,47.12 69.22,45.85 71.12,45.85 71.12,57.91 72.39,59.18 IC7.6
N$37
  Top 0.254: R22.2 19.05,19.18 20.32,17.91 20.32,16 Q1.2
OCLK  (via drill 0.61)
  Top 0.254: v30.48,40.77 30.48,66.8 27.31,69.98 IC9.14
  Bottom 0.254: v30.48,40.77 49.53,40.77 51.44,38.86 73.03,38.86 78.74,33.15 107.95,33.15 109.86,31.24 X1.9
OSELECT
  Top 0.254: IC7.12 64.77,69.34 67.31,71.88 IC6.4
  Bottom 0.254: X1.4 111.12,44.58 113.67,44.58 116.21,47.12 116.21,66.17 80.01,66.17 74.93,71.25 69.22,71.25 67.95,72.52 IC6.4
PIN22
  Bottom 0.254: X1.22 112.4,29.34 107.31,29.34 104.14,32.51 66.04,32.51 PIN22.2
RESET  (via drill 0.61)
  Top 0.254: v24.13,22.35 24.13,64.26 20.32,68.07 IC9.8
  Bottom 0.254: v24.13,22.35 26.04,20.45 66.68,20.45 77.47,9.65 90.17,9.65 92.08,7.75 ST2.B2
RESET\  (via drill 0.61)
  Top 0.254: v56.52,65.53 57.15,66.17 57.15,80.77 59.06,82.68 67.31,82.68 67.31,82.04 IC6.11
  Bottom 0.254: R17.2 40.01,65.53 v56.52,65.53 59.06,62.99 66.04,62.99 66.68,63.63 87.63,63.63 95.25,56.01 114.3,56.01 114.3,47.75 113.67,47.12 111.76,47.12 111.76,48.39 110.49,49.66 X1.2
SELECT  (via drill 0.61)
  Top 0.254: v41.91,59.82 40.64,58.55 40.64,37.59 41.91,36.32 IC3.6 41.91,33.78 41.91,30.61 JP1.10 41.28,29.97 40.01,29.97 JP1.8 | JP1.12 45.09,29.97 46.36,29.97 JP1.14 47.62,29.97 48.9,29.97 JP1.16
  Bottom 0.254: JP1.2 32.39,29.97 33.66,29.97 JP1.4 34.93,29.97 36.2,29.97 JP1.6 37.47,29.97 38.73,29.97 JP1.8 | v41.91,59.82 59.06,59.82 IC7.1 | JP1.12 43.82,29.97 42.55,29.97 JP1.10
STROBE  (via drill 0.61)
  Top 0.254: v22.86,57.28 21.59,58.55 21.59,65.53 20.32,66.8 17.15,66.8 17.15,68.71 18.42,69.98 IC9.7
  Bottom 0.254: v22.86,57.28 38.1,57.28 38.73,57.91 67.31,57.91 67.31,56.64 IC4.11
STROBE\
  Bottom 0.254: IC9.13 27.94,68.07 29.21,66.8 58.42,66.8 59.06,66.17 65.41,66.17 66.68,67.44 IC7.11
VCC  (via drill 0.61)
  Top 0.762: IC9.20 27.94,85.85 41.28,85.85 41.28,83.95 IC8.14 | C5.1 55.25,41.4 59.69,45.85 59.69,46.48 IC4.1 59.69,49.02 59.69,54.1 IC4.14 59.69,56.64 57.79,58.55 57.79,62.99 | 57.79,62.99 57.79,64.9 59.69,66.8 IC7.14 | 79.38,64.26 79.38,56.64 77.47,54.74 C7.1 | 79.38,64.26 77.47,66.17 C8.1 | 79.38,76.96 77.47,78.87 C9.1 | 79.38,64.26 79.38,76.96 | 79.38,76.96 79.38,89.66 77.47,91.57 C10.1 | R23.2 24.13,10.29 24.13,11.56 R21.2 24.13,12.83 25.4,14.1 v25.4,22.35 | IC1.16 31.12,25.53 28.58,28.07 28.58,34.42 IC3.1 29.21,36.32 29.21,41.4 IC3.20 29.21,43.94 29.21,56.01 25.4,59.82 C11.1 | v56.52,62.99 57.79,62.99
  Bottom 0.762: 48.9,81.41 59.06,81.41 IC6.14 | 48.9,81.41 45.09,81.41 43.18,83.31 IC8.14 | 48.9,81.41 59.69,92.2 IC5.14 60.33,92.84 62.23,90.93 75.56,90.93 76.84,92.2 C10.1 | IC4.14 60.33,54.74 61.6,54.74 IC4.13 62.87,54.74 65.41,52.2 74.93,52.2 76.84,54.1 C7.1 | C6.1 97.79,22.99 96.52,21.72 75.56,21.72 73.03,24.26 IC2.20 71.75,24.89 53.98,24.89 52.71,23.62 C4.1 52.07,22.99 50.8,21.72 32.39,21.72 29.84,24.26 | R23.2 24.13,9.02 24.13,7.75 ST2.B29 | C11.1 26.04,60.45 37.47,60.45 40.01,62.99 C12.1 41.28,62.99 v56.52,62.99 | v25.4,22.35 27.31,24.26 29.84,24.26 | 29.84,24.26 31.12,24.26 IC1.16
VCCO
  Top 0.762: X1.10 109.86,28.07 106.68,31.24 106.68,43.94 109.86,47.12 X1.3 109.86,47.75 107.31,50.29 107.31,73.15 | 107.31,73.15 112.4,78.23 112.4,85.22 C1.+ | 107.31,73.15 103.51,69.34 103.51,56.64 93.34,56.64 IC10.3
